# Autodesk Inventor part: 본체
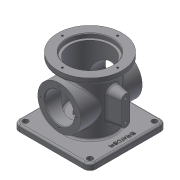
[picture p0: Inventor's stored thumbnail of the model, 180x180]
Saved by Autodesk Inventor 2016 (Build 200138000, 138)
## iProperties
Created: 2017-08
Part Number: 본체
Material: 알루미늄 6061
Document SubType Name: Modeling
Designer: mduedu
Density: 2.71 g/cm^3
Mass: 951.115 g
Surface Area: 966.539 cm^2
Volume: 350.965 cm^3
Appearance: 기본값
Author: mduedu
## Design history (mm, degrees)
sketch "스케치1"
  geometry: L1 (-62.5, -62.5)-(62.5, -62.5); L2 (62.5, -62.5)-(62.5, 62.5); L3 (62.5, 62.5)-(-62.5, 62.5); L4 (-62.5, 62.5)-(-62.5, -62.5); L5 (-62.5, -62.5)-(62.5, 62.5); L6 (62.5, -62.5)-(-62.5, 62.5); 1 further point
  constraints: 12 end point, 2 midpoint, 2 parallel, 1 horizontal, 1 perpendicular
  dimensions: "d232" = 125 distance of L3.end L2.end; "d233" = 125 distance of L2.end L1.end
extrude "돌출1" new body sketch "스케치1" distance "d5" = 10; taper "d6" = 0 deg
sketch "스케치2"
  geometry: C1 r 38 at (0, 0); 1 further point
  constraints: 1 centre point, 1 coincident
  dimensions: "d111" = 76 diameter of C1
extrude "돌출2" join sketch "스케치2" distance "d12" = 88; taper "d13" = 0 deg
sketch "스케치3"
  geometry: C1 r 52.5 at (0, 0); 1 further point
  constraints: 1 centre point, 1 coincident
  dimensions: "d114" = 105 diameter of C1
extrude "돌출3" join sketch "스케치3" distance "d19" = 10; taper "d20" = 0 deg
sketch "스케치4"
  geometry: C1 r 33 at (0, 0); 1 further point
  constraints: 1 centre point, 1 coincident
  dimensions: "d115" = 66 diameter of C1
extrude "돌출4" cut sketch "스케치4" distance "d26" = 86; taper "d27" = 0 deg
sketch "스케치5"
  geometry: C1 r 37 at (0, 0); 1 further point
  constraints: 1 centre point, 1 coincident
  dimensions: "d116" = 74 diameter of C1
extrude "돌출5" cut sketch "스케치5" distance "d29" = 7; taper "d30" = 0 deg
node "작업 평면1"
sketch "스케치18"
  geometry: L1 (-62.5, 0)-(62.5, 0) reference; C1 r 35 at (0, 54); 1 further point
  constraints: 1 centre point, 1 vertical alignment
  dimensions: "d118" = 70 diameter of C1; "d234" = 54 distance from line of C1.centre L1
extrude "돌출9" join sketch "스케치18" stored distance "d120" = 10; taper "d121" = 0 deg
hole "구멍8" diameter "d124" = 48; stored, may be unused: countersink angle "d128" = 90 deg, drill point angle "d130" = 118 deg; dims "d122" = 10, "d123" = 10, "d125" = 6, "d126" = 4, "d127" = 2, "d129" = 8
sketch "스케치9"
  geometry: C1 r 33 at (0, 0); 1 further point
  constraints: 1 centre point, 1 coincident
  dimensions: "d131" = 66 diameter of C1
extrude "돌출8" cut sketch "스케치9" distance "d43" = 16; taper "d44" = 0 deg
node "작업 평면2"
fillet "모깎기9" dims "d137" = 3
fillet "모깎기10" dims "d138" = 3
chamfer "모따기2" distance "d139" = 1; stored, may be unused: second distance "d140" = 2, angle "d141" = 45 deg
fillet "모깎기11" dims "d142" = 3
fillet "모깎기12" dims "d143" = 3
fillet "모깎기13" dims "d144" = 3
node "작업 평면3"
sketch "스케치20"
  geometry: L1 (108, -52.5)-(108, 52.5) reference; L2 (37, 7)-(71, 7); L3 (37, -7)-(71, -7); L4 (0, -33)-(0, 33) reference; A1 r 7 centre (37, 0) between (37, 7) and (37, -7); A2 r 7 centre (71, 0) between (71, 7) and (71, -7); 1 further point
  constraints: 4 end point, 4 point on circle, 3 tangent, 2 centre point, 2 horizontal alignment, 1 parallel, 1 perpendicular
  dimensions: "d203" = 14 diameter of A1; "d206" = 30 distance edge to line of A2 L1; "d207" = 48 dimension on A2 A1 (derived); "d236" = 30 distance edge to line of A1 L4
extrude "돌출10" join sketch "스케치20" stored distance "d152" = 10; taper "d153" = 10 deg
sketch "스케치21"
  geometry: C1 r 7 at (0, 71) reference; C2 r 7 at (0, 37) reference; 3 further points
  constraints: 2 coincident
hole "구멍12" sketch "스케치21" at (0, 71), (0, 37) diameter "d219" = 4.134; stored, may be unused: countersink angle "d223" = 90 deg, drill point angle "d225" = 118 deg; dims "d220" = 6, "d221" = 4, "d222" = 2, "d224" = 8
fillet "모깎기18" dims "d229" = 3
sketch "스케치23"
  geometry: C1 r 20 at (0, 0); 1 further point
  constraints: 1 centre point, 1 coincident
  dimensions: "d168" = 40 diameter of C1
extrude "돌출12" cut sketch "스케치23" stored distance "d169" = 148.25; taper "d170" = 0 deg
sketch "스케치28"
  geometry: L1 (62.5, -62.5)-(62.5, 62.5) reference; 2 further points
  constraints: 1 horizontal alignment, 1 other
  dimensions: "d238" = 10 distance from line of point (52.5, 0) L1
feature "엠보싱4" sketch "스케치28" dims "d239" = 0.5, "d240" = 0
sketch "스케치25" dims "d178" = 58
  geometry: C1 r 35 at (0, 0) reference; 3 further points
  constraints: 2 vertical alignment, 1 coincident, 2 other
hole "구멍10" sketch "스케치25" at (0, 29) diameter "d179" = 3.242; stored, may be unused: countersink angle "d183" = 90 deg, drill point angle "d185" = 118 deg; dims "d180" = 4, "d181" = 4, "d182" = 2, "d184" = 6
sketch "스케치26" dims "d189" = 90
  geometry: 3 further points
  constraints: 2 vertical alignment, 1 coincident, 2 other
hole "구멍11" sketch "스케치26" at (0, 45) diameter "d190" = 3.242; stored, may be unused: countersink angle "d194" = 90 deg, drill point angle "d196" = 118 deg; dims "d191" = 4, "d192" = 4, "d193" = 2, "d195" = 6
chamfer "모따기4" distance "d200" = 1; stored, may be unused: second distance "d201" = 2, angle "d202" = 45 deg
fillet "모깎기19" dims "d241" = 10
sketch "스케치29"
  geometry: A1 r 10 centre (-52.5, 52.5) between (-52.5, 62.5) and (-62.5, 52.5) reference; A2 r 10 centre (52.5, 52.5) between (62.5, 52.5) and (52.5, 62.5) reference; A3 r 10 centre (52.5, -52.5) between (52.5, -62.5) and (62.5, -52.5) reference; A4 r 10 centre (-52.5, -52.5) between (-62.5, -52.5) and (-52.5, -62.5) reference; 5 further points
  constraints: 4 coincident
hole "구멍13" sketch "스케치29" at (-52.5, 52.5), (52.5, 52.5), (52.5, -52.5), (-52.5, -52.5) diameter "d242" = 9; stored, may be unused: countersink angle "d246" = 90 deg, drill point angle "d248" = 118 deg; dims "d243" = 6, "d244" = 4, "d245" = 2, "d247" = 8
fillet "모깎기20" dims "d249" = 3
node "솔리드1"
mirror "대칭2"
pattern_circular "원형 패턴1" dims angle "d187" = 360 deg
mirror "대칭3"
pattern_circular "원형 패턴2" dims angle "d198" = 360 deg
other parameters: "d147" = 58
